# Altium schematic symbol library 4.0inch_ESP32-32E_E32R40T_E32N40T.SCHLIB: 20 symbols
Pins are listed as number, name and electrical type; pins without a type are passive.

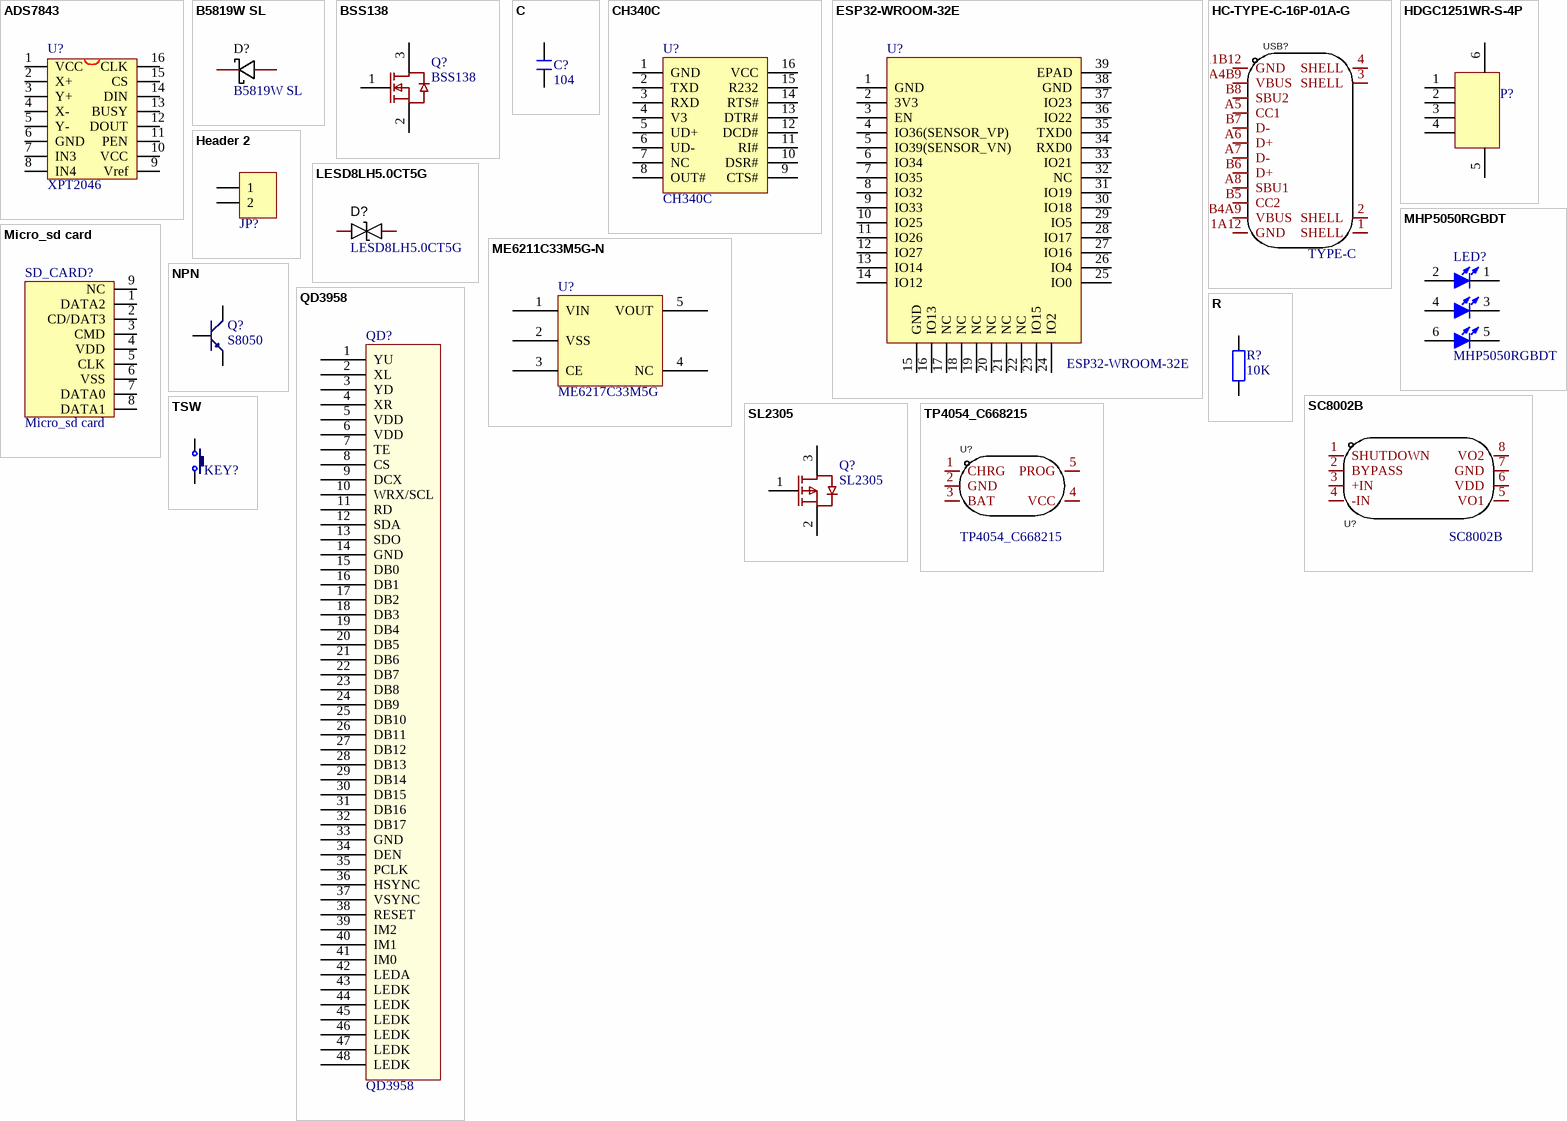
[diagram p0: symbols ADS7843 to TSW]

## ADS7843
designator U?, comment XPT2046
footprint SSOP16
pins: 1 VCC, 2 X+, 3 Y+, 4 X-, 5 Y-, 6 GND, 7 IN3, 8 IN4, 9 Vref, 10 VCC, 11 PEN, 12 DOUT, 13 BUSY, 14 DIN, 15 CS, 16 CLK

## B5819W SL
designator D?
Manufacturer: CJ(江苏长电/长晶); Symbol: B5819W_C8598; Add into BOM: yes; Forward Voltage (Vf@If): 600mV@1A; Reverse Voltage (Vr): 40V; Average Rectified Current (Io): 1A
footprint SOD-123_L2.7-W1.6-LS3.7-RD-1
pins: 1 -, 2 +

## BSS138
designator Q?
footprint SOT-23-3_L2.9-W1.3-P1.90-LS2.4-BR
pins: 1 G, 2 S, 3 D

## C
designator C?, comment 104
无极性贴片电容; 版权归属: 源创客; 材质: X7R
footprint C 0603 (无极性贴片电容)
pins: 1, 2

## CH340C
designator U?
USB转串口IC
footprint SOP-16_L10.0-W3.9-P1.27-LS6.0-BL
pins: 1 GND, 2 TXD, 3 RXD, 4 V3, 5 UD+, 6 UD-, 7 NC, 8 OUT#, 9 CTS#, 10 DSR#, 11 RI#, 12 DCD#, 13 DTR#, 14 RTS#, 15 R232, 16 VCC

## ESP32-WROOM-32E
designator U?
ESP32-WROOM-32E module
footprint ESP32-WROOM-32E
pins: 1 GND, 2 3V3, 3 EN, 4 IO36(SENSOR_VP), 5 IO39(SENSOR_VN), 6 IO34, 7 IO35, 8 IO32, 9 IO33, 10 IO25, 11 IO26, 12 IO27, 13 IO14, 14 IO12, 15 GND, 16 IO13, 17 NC, 18 NC, 19 NC, 20 NC, 21 NC, 22 NC, 23 IO15, 24 IO2, 25 IO0, 26 IO4, 27 IO16, 28 IO17, 29 IO5, 30 IO18, 31 IO19, 32 NC, 33 IO21, 34 RXD0, 35 TXD0, 36 IO22, 37 IO23, 38 GND, 39 EPAD

## HC-TYPE-C-16P-01A-G
designator USB?, comment TYPE-C
Manufacturer: HCTL(华灿天禄); Name: HC-TYPE-C-16P-01A-G; Add into BOM: yes; Gender: 母座; Number of Contacts: 16; Number of Ports: 1
3D model USB-C-SMD_G-SWITCH_GT-USB-7010EN
footprint USB-C-SMD_G-SWITCH_GT-USB-7010EN
footprint USB-C-SMD_G-SWITCH_GT-USB-7010EN
pins: 1 SHELL, 2 SHELL, 3 SHELL, 4 SHELL, A1B12 GND, A4B9 VBUS, A5 CC1, A6 D+, A7 D-, A8 SBU1, B1A12 GND, B4A9 VBUS, B5 CC2, B6 D+, B7 D-, B8 SBU2

## HDGC1251WR-S-4P
designator P?  (value not drawn)
footprint CONN-SMD_4P-P1.25_HDGC-HDGC1251WR-S-4P
pins: 1, 2, 3, 4, 5, 6

## Header 2
designator JP?  (value not drawn)
2P接插件; BOM名称: 20*2P接插件; 版权归属: 源创客
footprint CONN-SMD_HC-1.25-2PLT
pins: 1, 2

## LESD8LH5.0CT5G
designator D?
Manufacturer: LRC(乐山无线电); Add into BOM: yes; Reverse Stand-Off Voltage (Vrwm): 5V; Maximum Clamping Voltage: 11.5V; Peak Pulse Current (Ipp)@10/1000us: 3.5A@8/20us; Breakdown Voltage: 5.5V; Type: TVS
footprint SOD-882_L1.0-W0.6-BI
pins: 1, 2

## ME6211C33M5G-N
designator U?, comment ME6217C33M5G
稳压芯片
footprint SOT-23-5_L3.0-W1.7-P0.95-LS2.8-BL
pins: 1 VIN, 2 VSS, 3 CE, 4 NC, 5 VOUT

## MHP5050RGBDT
designator LED?
RGB LED
footprint LED-ARRAY-SMD_6P-L5.0-W5.0-TR-RD
pins: 1 K, 2 A, 3 K, 4 A, 5 K, 6 A

## Micro_sd card
designator SD_CARD?
miniSD卡卡槽
footprint MicroTF
pins: 1 DATA2, 2 CD/DAT3, 3 CMD, 4 VDD, 5 CLK, 6 VSS, 7 DATA0, 8 DATA1, 9 NC

## NPN
designator Q?, comment S8050
8050/BCW846/BCW847
footprint SOT-23R
footprint NPN
pins: 1 E, 2 B, 3 C

## QD3958
designator QD?
footprint 3.5-QD3503 (3.5 TFT LCD)
pins: 1 YU, 2 XL, 3 YD, 4 XR, 5 VDD, 6 VDD, 7 TE, 8 CS, 9 DCX, 10 WRX/SCL, 11 RD, 12 SDA, 13 SDO, 14 GND, 15 DB0, 16 DB1, 17 DB2, 18 DB3, 19 DB4, 20 DB5, 21 DB6, 22 DB7, 23 DB8, 24 DB9, 25 DB10, 26 DB11, 27 DB12, 28 DB13, 29 DB14, 30 DB15, 31 DB16, 32 DB17, 33 GND, 34 DEN, 35 PCLK, 36 HSYNC, 37 VSYNC, 38 RESET, 39 IM2, 40 IM1, 41 IM0, 42 LEDA, 43 LEDK, 44 LEDK, 45 LEDK, 46 LEDK, 47 LEDK, 48 LEDK

## R
designator R?, comment 10K
贴片电阻; 版权归属: 源创客
footprint R0603
pins: 1, 2

## SC8002B
designator U?
Manufacturer: FM(富满); Add into BOM: yes; Speaker Channels: 单声道; Output Power: 2.5Wx1@4Ω; Supply Voltage: 2V~5V
footprint SOP-8_L4.9-W3.9-P1.27-LS6.0-BL
pins: 1 SHUTDOWN, 2 BYPASS, 3 +IN, 4 -IN, 5 VO1, 6 VDD, 7 GND, 8 VO2

## SL2305
designator Q?
P-mos
footprint SOT-23
pins: 1 G, 2 S, 3 D

## TP4054_C668215
designator U?
Manufacturer: UMW(友台半导体); Manufacturer Part: TP4054; Add into BOM: yes; Supply Voltage: 6.5V; Maximum Charge Current: 500mA; Type of Battery: 锂离子/聚合物; Number of Cells: 1
footprint TSOT-23-5_L2.9-W1.6-P0.95-LS2.8-BR
pins: 1 CHRG, 2 GND, 3 BAT, 4 VCC, 5 PROG

## TSW
designator KEY?, comment 3x6x5  (value not drawn)
轻触开关; BOM名称: 3x6轻触开关; 版权归属: 源创客
footprint TSW SMD-3*4*2.5 (3*4*2.5mm)
pins: 1, 2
